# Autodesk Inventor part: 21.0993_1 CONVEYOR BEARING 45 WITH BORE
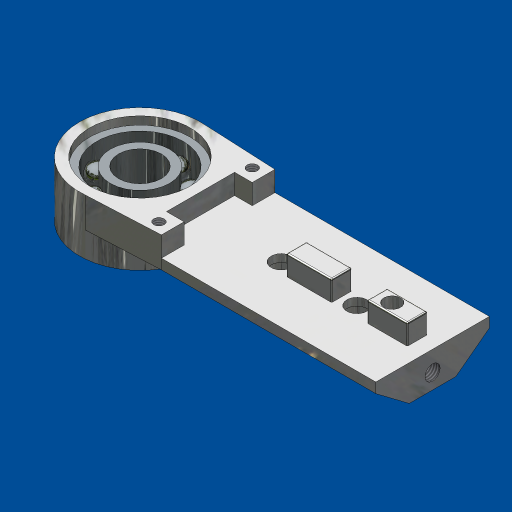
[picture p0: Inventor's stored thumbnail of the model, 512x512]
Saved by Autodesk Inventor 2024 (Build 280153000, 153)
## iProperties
Created: 2007-04
Part Number: 21.0993_1 CONVEYOR BEARING 45 WITH BORE
Document SubType Name: Modeling
Designer: Andy Moles
Material: Aluminum-6061
Mass: 199.951 g
Surface Area: 277.121 cm^2
Volume: 73.7826 cm^3
Density: 2.71 g/cm^3
Appearance: Anodized - White
Author: Andy Moles
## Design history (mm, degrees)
feature "Base1"
hole "Hole1" diameter "d2" = 6; stored, may be unused: countersink angle "d6" = 90 deg, drill point angle "d8" = 0 deg; dims "d0" = 10, "d1" = 10, "d3" = 6, "d4" = 4, "d5" = 2, "d7" = 28
thread "Thread1" dims "d9" = 10, "d10" = 0
sketch "Sketch1"
  geometry: C1 r 24 at (-22.154, 9.23); A1 r 24 centre (-22.154, 9.23) between (0, 18.459) and (0, 0) reference; 1 further point
  constraints: 1 centre point, 1 coincident, 1 concentric
extrude "Extrusion1" join sketch "Sketch1" distance "d11" = 2.8; taper "d12" = 0 deg
sketch "Sketch2"
  geometry: L1 (31, 22.5)-(31, -22.5) reference; L2 (24, -13.5)-(51.382, -13.5); L3 (51.382, -13.5)-(51.382, 13.5); L4 (51.382, 13.5)-(24, 13.5); L5 (24, 13.5)-(24, -13.5); C1 r 20.001 at (0, 0) reference; 2 further points
  constraints: 8 end point, 2 parallel, 1 horizontal, 1 horizontal alignment, 1 midpoint, 1 perpendicular
  dimensions: "d13" = 27 distance of L2.end L3.end; "d14" = 7 distance between parallel lines of L5 L1
extrude "Extrusion2" cut sketch "Sketch2" stored distance "d15" = 10; taper "d16" = 0 deg
sketch "Sketch3"
  geometry: L1 (31, 22.5)-(31, 13.5) reference; L2 (31, -13.5)-(31, -22.5) reference; L3 (116, 22.5)-(31, 22.5) reference; L4 (116, -22.5)-(31, -22.5) reference; 3 further points
  dimensions: "d24" = 5 distance from line of point (26, -18.5) L2; "d25" = 5 distance from line of point (26, 18.5) L1; "d26" = 4 distance from line of point (26, 18.5) L3; "d27" = 4 distance from line of point (26, -18.5) L4
hole "Hole2" sketch "Sketch3" at (26, -18.5), (26, 18.5) diameter "d17" = 4.134; stored, may be unused: countersink angle "d21" = 90 deg, drill point angle "d23" = 118 deg; dims "d18" = 6, "d19" = 4, "d20" = 2, "d22" = 7
sketch "Sketch4"
  geometry: L1 (0, 0)-(18, 0) reference; L2 (18, 8)-(18, 0) reference; L3 (0, 8)-(18, 8) reference; L4 (0, 0)-(0, 8) reference; 1 further point
extrude "Extrusion3" join sketch "Sketch4" distance "d28" = 5; taper "d29" = 0 deg
sketch "Sketch5"
  geometry: L1 (49, 26.5)-(49, 18.5) reference; L2 (63, 26.5)-(79, 26.5); L3 (79, 26.5)-(79, 18.5); L4 (79, 18.5)-(63, 18.5); L5 (63, 18.5)-(63, 26.5); L6 (49, 26.5)-(31, 26.5) reference; L7 (31, 18.5)-(49, 18.5) reference; 1 further point
  constraints: 8 end point, 2 collinear, 2 parallel, 1 horizontal, 1 perpendicular
  dimensions: "d30" = 16 distance of L2.start L2.end; "d31" = 14 distance between parallel lines of L5 L1
extrude "Extrusion4" join sketch "Sketch5" distance "d32" = 8; taper "d33" = 0 deg
fillet "Fillet1" dims "d34" = 0.5
sketch "Sketch6"
  geometry: C1 r 20 at (-22.154, 9.23) reference; C2 r 9.5 at (-22.154, 9.23); 1 further point
  constraints: 1 centre point, 1 coincident
  dimensions: "d35" = 19 diameter of C2
extrude "Extrusion5" cut sketch "Sketch6" stored distance "d36" = 10; taper "d37" = 0 deg
sketch "Sketch7"
  geometry: L1 (93.846, 0)-(93.846, 18.459) reference; C1 r 9.5 at (-22.154, 9.23) reference; 3 further points
  constraints: 1 horizontal alignment, 1 midpoint
  dimensions: "d38" = 100 distance of point (77.846, 9.23) C1.centre
hole "Hole3" sketch "Sketch7" at (77.846, 9.23) diameter "d39" = 6.647; stored, may be unused: countersink angle "d43" = 90 deg, drill point angle "d45" = 118 deg; dims "d40" = 16, "d41" = 13, "d42" = 15.3, "d44" = 8
body "Solid1"
